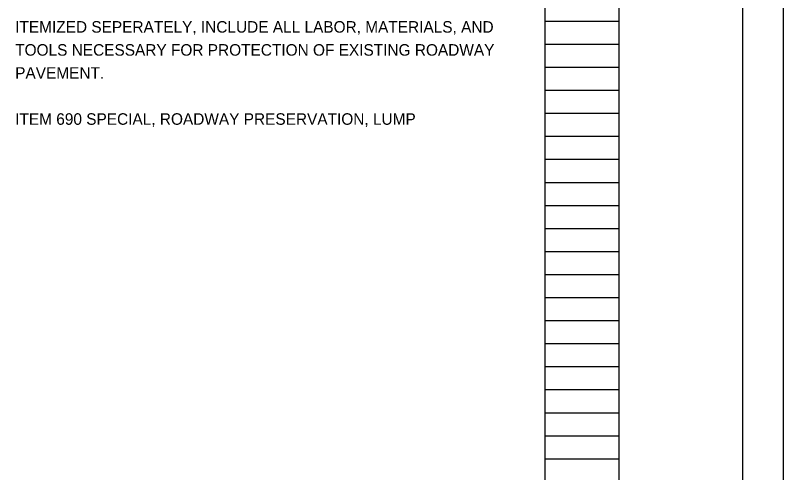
# Model space of a CAD drawing. Extents: x 0 to 34, y 0 to 22.
# Drawn here: x 24.66 to 34, y 5.57 to 11.13 of the extents above; entities that cross this region are included whole.
import ezdxf

# ---------------------------------------------------------------- set-up
doc = ezdxf.new("R2010")
doc.units = 0
for name, color, linetype in [('CS-ALGN-CNTR', 7, 'Continuous'), ('CS-ALGN-TEXT', 7, 'Continuous'), ('CS-ANNO-MATC', 7, 'Continuous'), ('CS-ANNO-MATC-MASK', 7, 'Continuous')]:
    doc.layers.add(name, color=color, linetype=linetype)

msp = doc.modelspace()

# ---------------------------------------------------------------- linework, layer by layer
at = {"layer": 'CS-ALGN-CNTR'}
msp.add_lwpolyline([(0, 0), (34, 0), (34, 22), (0, 22)], close=True, dxfattribs=at)
at = {"layer": 'CS-ALGN-TEXT'}
msp.add_line((32, 0.5), (32, 21.5), dxfattribs=at)
msp.add_lwpolyline([(1.5, 21.5), (33.5, 21.5), (33.5, 0.5), (1.5, 0.5)], close=True, dxfattribs=at)
at = {"layer": 'CS-ANNO-MATC-MASK'}
for p, q in [((31.0995, 0.9796), (31.0995, 21.1396)), ((31.9995, 0.9796), (31.9995, 21.1396)), ((31.0995, 11.0596), (31.9995, 11.0596)), ((31.0995, 10.7796), (31.9995, 10.7796)), ((31.0995, 10.4996), (31.9995, 10.4996)), ((31.0995, 10.2196), (31.9995, 10.2196)), ((31.0995, 9.9396), (31.9995, 9.9396)), ((31.0995, 9.6596), (31.9995, 9.6596)), ((31.0995, 9.3796), (31.9995, 9.3796)), ((31.0995, 9.0996), (31.9995, 9.0996)), ((31.0995, 8.8196), (31.9995, 8.8196)), ((31.0995, 8.5396), (31.9995, 8.5396)), ((31.0995, 8.2596), (31.9995, 8.2596)), ((31.0995, 7.9796), (31.9995, 7.9796)), ((31.0995, 7.6996), (31.9995, 7.6996)), ((31.0995, 7.4196), (31.9995, 7.4196)), ((31.0995, 7.1396), (31.9995, 7.1396)), ((31.0995, 6.8596), (31.9995, 6.8596)), ((31.0995, 6.5796), (31.9995, 6.5796)), ((31.0995, 6.2996), (31.9995, 6.2996)), ((31.0995, 6.0196), (31.9995, 6.0196)), ((31.0995, 5.7396), (31.9995, 5.7396))]:
    msp.add_line(p, q, dxfattribs=at)

# ---------------------------------------------------------------- texts
at = {"layer": 'CS-ANNO-MATC'}
for s, p in [('ITEMIZED SEPERATELY, INCLUDE ALL LABOR, MATERIALS, AND ', (24.6595, 10.9196)), ('TOOLS NECESSARY FOR PROTECTION OF EXISTING ROADWAY ', (24.6595, 10.6396)), ('PAVEMENT.', (24.6595, 10.3596)), ('ITEM 690 SPECIAL, ROADWAY PRESERVATION, LUMP', (24.6595, 9.7996))]:
    msp.add_text(s, height=0.14, dxfattribs=at).set_placement(p)

doc.saveas('drawing.dxf')
